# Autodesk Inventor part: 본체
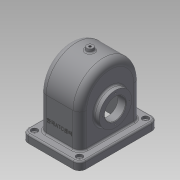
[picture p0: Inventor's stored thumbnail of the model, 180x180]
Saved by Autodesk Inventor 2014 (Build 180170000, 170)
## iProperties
Created: 2016-10
Part Number: 본체
Material: 일반
Document SubType Name: Modeling
Designer: q
Density: 1 g/cm^3
Appearance: 기본값
Mass: 429.775 g
Surface Area: 1201.17 cm^2
Volume: 429.775 cm^3
Author: q
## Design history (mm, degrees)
sketch "스케치1"
  geometry: L1 (-55, 75)-(55, 75); L2 (55, 75)-(55, -75); L3 (55, -75)-(-55, -75); L4 (-55, -75)-(-55, 75); L5 (-55, 75)-(55, -75); L6 (55, 75)-(-55, -75); 3 further points
  constraints: 12 end point, 3 midpoint, 2 parallel, 1 coincident, 1 horizontal, 1 perpendicular
  dimensions: "d0" = 110 distance of L1.start L1.end; "d1" = 150 distance of L3.end L1.start
extrude "돌출1" new body sketch "스케치1" distance "d2" = 15; taper "d3" = 0 deg
fillet "모깎기1" dims "d4" = 12
sketch "스케치2"
  geometry: A1 r 12 centre (-43, 63) between (-43, 75) and (-55, 63) reference; A2 r 12 centre (-43, -63) between (-55, -63) and (-43, -75) reference; A3 r 12 centre (43, -63) between (43, -75) and (55, -63) reference; A4 r 12 centre (43, 63) between (55, 63) and (43, 75) reference; 1 further point
hole "구멍1" sketch "스케치2" at (-43, 63), (-43, -63), (43, -63), (43, 63) diameter "d5" = 5; stored, may be unused: countersink angle "d9" = 90 deg, drill point angle "d11" = 118 deg; dims "d6" = 6, "d7" = 12, "d8" = 5, "d10" = 8
fillet "모깎기2" dims "d12" = 3
sketch "스케치3"
  geometry: L1 (75, 12)-(75, 0) reference; L2 (75, 0)-(-75, 0) reference; L3 (-75, 0)-(-75, 12) reference; L4 (-72, 15)-(72, 15) reference; L5 (-58, 80)-(-58, 15); L6 (58, 80)-(58, 15); A1 r 3 centre (72, 12) between (75, 12) and (72, 15) reference; A2 r 3 centre (-72, 12) between (-72, 15) and (-75, 12) reference; A3 r 58 centre (0, 80) between (58, 80) and (-58, 80); 2 further points
  constraints: 4 end point, 2 point on circle, 2 point on line, 2 tangent, 2 vertical, 1 centre point, 1 midpoint, 1 vertical alignment
  dimensions: "d13" = 80 distance from line of L2 A3.centre; "d14" = 116 diameter of A3
extrude "돌출2" join sketch "스케치3" stored distance "d15" = 77; taper "d16" = 0 deg
sketch "스케치4"
  geometry: L1 (0, 63)-(0, -63) reference; C1 r 31 at (-65, 0); A1 r 58 centre (-80, 0) between (-80, 58) and (-80, -58) reference; 1 further point
  constraints: 1 centre point, 1 horizontal alignment
  dimensions: "d17" = 62 diameter of C1; "d18" = 65 distance from line of L1 C1.centre
extrude "돌출3" join sketch "스케치4" distance "d19" = 10; taper "d20" = 0 deg
sketch "스케치5"
  geometry: C1 r 31 at (0, 0) reference; 5 further points
  constraints: 1 vertical alignment, 5 other
  dimensions: "d21" = 26 distance of C1.centre point (0, -26); "d24" = 360 deg dimension on C1.centre point (0, -26) (derived)
hole "구멍2" sketch "스케치5" at (0, -26), (26, 0), (0, 26), (-26, 0) diameter "d26" = 2.459; stored, may be unused: countersink angle "d30" = 90 deg, drill point angle "d32" = 118 deg; dims "d27" = 6, "d28" = 12, "d29" = 5, "d31" = 8
sketch "스케치6"
  geometry: C1 r 37.5 at (65, 0); C2 r 31 at (65, 0) reference; 1 further point
  constraints: 1 centre point, 1 coincident
  dimensions: "d33" = 75 diameter of C1
extrude "돌출4" join sketch "스케치6" distance "d34" = 5; taper "d35" = 0 deg
sketch "스케치7"
  geometry: C1 r 37.5 at (0, 0) reference; 5 further points
  constraints: 1 vertical alignment, 5 other
  dimensions: "d36" = 29 distance of C1.centre point (0, 29); "d39" = 360 deg dimension on C1.centre point (0, 29) (derived)
hole "구멍3" sketch "스케치7" at (0, 29), (-29, 0), (0, -29), (29, 0) diameter "d41" = 2.459; stored, may be unused: countersink angle "d45" = 90 deg, drill point angle "d47" = 118 deg; dims "d42" = 6, "d43" = 12, "d44" = 5, "d46" = 8
sketch "스케치8"
  geometry: L1 (75, 12)-(75, 0) reference; L2 (75, 0)-(-75, 0) reference; L3 (-75, 0)-(-75, 12) reference; L4 (-72, 15)-(-58, 15) reference; L5 (-58, 15)-(-58, 80) reference; L6 (58, 80)-(58, 15) reference; L7 (58, 15)-(72, 15) reference; L8 (-52, 80)-(-52, 0); L9 (52, 0)-(52, 80); A1 r 3 centre (72, 12) between (75, 12) and (72, 15) reference; A2 r 3 centre (-72, 12) between (-72, 15) and (-75, 12) reference; A3 r 58 centre (0, 80) between (58, 80) and (-58, 80) reference; A4 r 52 centre (0, 80) between (52, 80) and (-52, 80)
  constraints: 4 end point, 2 point on circle, 2 point on line, 1 centre point
  dimensions: "d48" = 6 radial gap between concentric circles of A4 A3; "d49" = 6 distance between parallel lines of L5 L8; "d51" = 6 distance between parallel lines of L6 L9
extrude "돌출5" cut sketch "스케치8" stored distance "d52" = 67; taper "d53" = 0 deg
sketch "스케치9"
  geometry: C1 r 31 at (0, 0) reference; 1 further point
hole "구멍4" sketch "스케치9" at (0, 0) diameter "d54" = 40; stored, may be unused: countersink angle "d58" = 90 deg, drill point angle "d60" = 118 deg; dims "d55" = 6, "d56" = 12, "d57" = 5, "d59" = 8
sketch "스케치10"
  geometry: L1 (-48.5, 96)-(-38.5, 96) reference; L2 (-38.5, 96)-(-38.5, 138) reference; L3 (-38.5, 138)-(38.5, 138) reference; L4 (38.5, 138)-(38.5, 102.5) reference; L5 (38.5, 102.5)-(43.5, 102.5) reference; L6 (43.5, 102.5)-(43.5, 95.23) reference; L7 (43.5, 95.23)-(35.5, 95.23) reference; L8 (35.5, 95.23)-(34.761, 94) reference; L9 (34.761, 94)-(35.5, 92.771) reference; L10 (35.5, 92.771)-(43.5, 92.771) reference; L11 (43.5, 92.771)-(43.5, 85) reference; L12 (43.5, 85)-(33.5, 85) reference; L13 (33.5, 85)-(33.5, 132) reference; L14 (33.5, 132)-(-33.5, 132) reference; L15 (-33.5, 132)-(-33.5, 85) reference; L16 (-33.5, 85)-(-48.5, 85) reference; L17 (-48.5, 85)-(-48.5, 89.77) reference; L18 (-48.5, 89.77)-(-40.5, 89.77) reference; L19 (-40.5, 89.77)-(-39.761, 91) reference; L20 (-39.761, 91)-(-40.5, 92.229) reference; L21 (-40.5, 92.229)-(-48.5, 92.229) reference; L22 (-48.5, 92.229)-(-48.5, 96) reference; L23 (-52, 15)-(-38.5, 15) reference; L24 (-38.5, 15)-(-38.5, 34) reference; L25 (-38.5, 34)-(-48.5, 34) reference; L26 (-48.5, 34)-(-48.5, 37.77) reference; L27 (-48.5, 37.77)-(-40.5, 37.77) reference; L28 (-40.5, 37.77)-(-39.761, 39) reference; L29 (-39.761, 39)-(-40.5, 40.23) reference; L30 (-40.5, 40.23)-(-48.5, 40.23) reference; L31 (-48.5, 40.23)-(-48.5, 45) reference; L32 (-48.5, 45)-(-33.5, 45) reference; L33 (-33.5, 45)-(-33.5, 0) reference; L34 (-33.5, 0)-(-55, 0) reference; L35 (-55, 0)-(-55, 12) reference; L36 (55, 12)-(55, 0) reference; L37 (55, 0)-(33.5, 0) reference; L38 (33.5, 0)-(33.5, 45) reference; L39 (33.5, 45)-(43.5, 45) reference; L40 (43.5, 45)-(43.5, 37.229) reference; L41 (43.5, 37.229)-(35.5, 37.229) reference; L42 (35.5, 37.229)-(34.761, 36) reference; L43 (34.761, 36)-(35.5, 34.77) reference; L44 (35.5, 34.77)-(43.5, 34.77) reference; L45 (43.5, 34.77)-(43.5, 27.5) reference; L46 (43.5, 27.5)-(38.5, 27.5) reference; L47 (38.5, 27.5)-(38.5, 15) reference; L48 (38.5, 15)-(52, 15) reference; L49 (33.5, 104.747)-(19.5, 93); L50 (19.5, 93)-(19.5, 65); L51 (33.5, 65)-(19.5, 65); L52 (-33.5, 0)-(33.5, 0) reference; L53 (33.5, 45)-(33.5, 85) reference; A1 r 3 centre (-52, 12) between (-52, 15) and (-55, 12) reference; A2 r 3 centre (52, 12) between (55, 12) and (52, 15) reference; 1 further point
  constraints: 6 end point, 1 horizontal, 1 midpoint, 1 point on line, 1 vertical
  dimensions: "d61" = 65 distance between parallel lines of L52 L51; "d62" = 28 distance of L49.end L50.end; "d63" = 50 deg angle of L50 L49; "d64" = 14 distance of L51.start L50.end
revolve "회전1" sketch "스케치10" stored, may be unused: angle "d65" = 90 deg
sketch "스케치11"
  geometry: C1 r 20 at (0, 0) reference; 1 further point
hole "구멍5" sketch "스케치11" at (0, 0) diameter "d66" = 40; stored, may be unused: countersink angle "d70" = 90 deg, drill point angle "d72" = 118 deg; dims "d67" = 6, "d68" = 12, "d69" = 5, "d71" = 8
node "작업 평면1"
sketch "스케치12"
  geometry: C1 r 6 at (0, 0); 1 further point
  constraints: 1 centre point, 1 coincident
  dimensions: "d74" = 12 diameter of C1
extrude "돌출6" join sketch "스케치12" distance "d75" = 7; taper "d76" = 0 deg
sketch "스케치13"
  geometry: C1 r 6 at (0, 0) reference
hole "구멍6" sketch "스케치13" at (0, 0) diameter "d77" = 4.459; stored, may be unused: countersink angle "d81" = 90 deg, drill point angle "d83" = 118 deg; dims "d78" = 6, "d79" = 12, "d80" = 5, "d82" = 8
fillet "모깎기4" dims "d86" = 3
fillet "모깎기5" dims "d87" = 13
fillet "모깎기6" dims "d88" = 3
fillet "모깎기7" dims "d89" = 8
node "작업 평면2"
sketch "스케치14"
  geometry: L1 (68.5, -80)-(-17.5, -80) reference; L2 (-13, 0)-(-13, -62) reference; 2 further points
  constraints: 1 other
  dimensions: "d91" = 40 distance from line of L1 point (25.5, -40); "d92" = 38.5 distance from line of point (25.5, -40) L2
feature "엠보싱1" sketch "스케치14" dims "d0" = 110, "d1" = 150, "d93" = 0.5, "d94" = 0
chamfer "모따기1" distance "d95" = 1; stored, may be unused: second distance "d96" = 2, angle "d97" = 45 deg
fillet "모깎기8" dims "d98" = 3
feature "면 기울기2" dims angle "d99" = 10 deg
fillet "모깎기9" dims "d100" = 3
node "솔리드1"
node "절단 모서리 투영1"
node "절단 모서리 투영2"
node "절단 모서리 투영3"
other parameters: "d73" = -144, "d90" = 44.25
